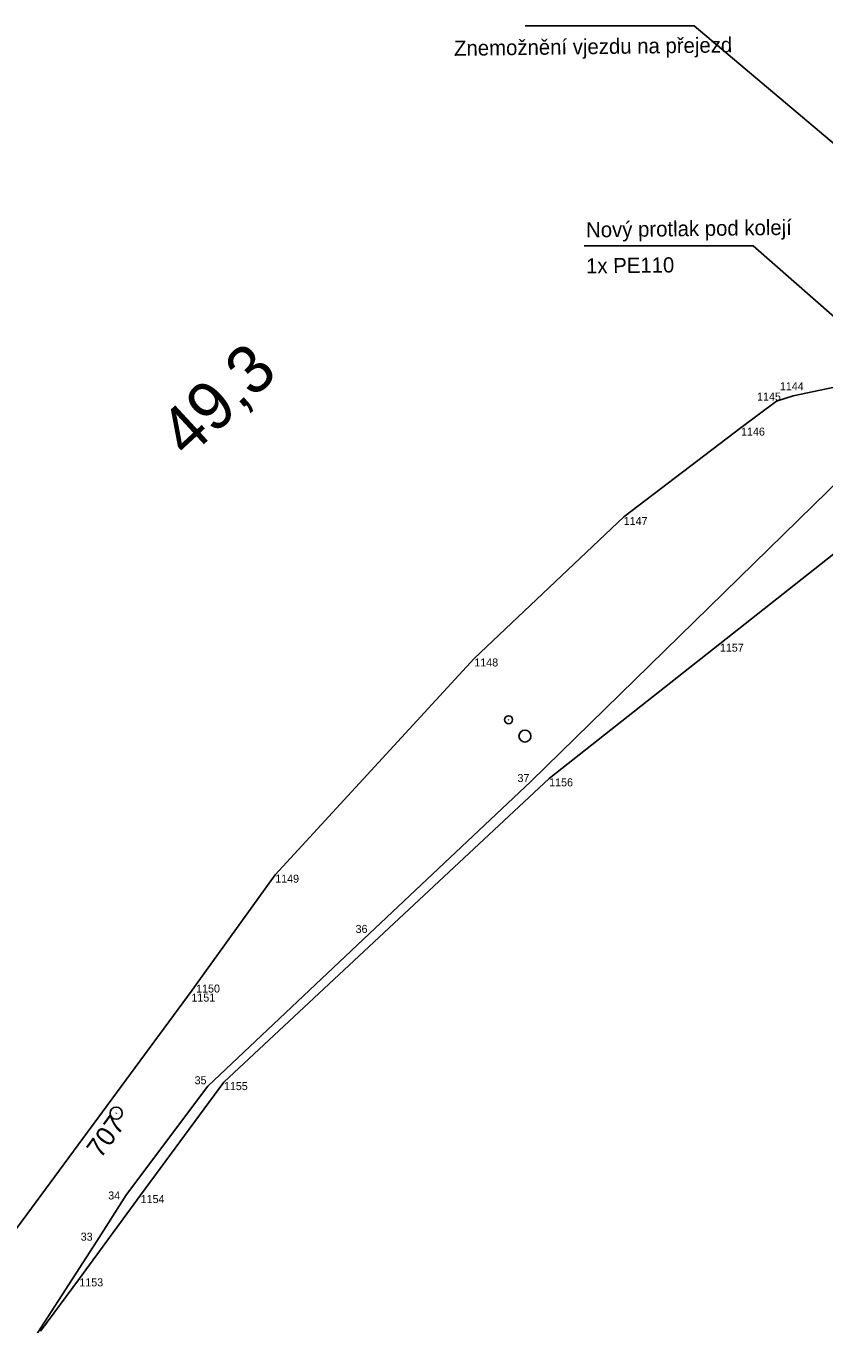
# Model space of a CAD drawing. Extents: x -678683 to -677755, y -1006946 to -1005971.
# Drawn here: x -678402.7 to -678303, y -1006633.5 to -1006471.2 of the extents above; entities that cross this region are included whole.
import ezdxf

# ---------------------------------------------------------------- set-up
doc = ezdxf.new("R2010")
doc.units = 0
for name, color, linetype in [('SSZT nové - lomové body', 7, 'Continuous'), ('SSZT_nové', 7, 'Continuous'), ('Stávající ŽBP', 7, 'Continuous'), ('SŽDC', 7, 'Continuous'), ('SŽDC - body', 7, 'Continuous'), ('Vrstva 7', 7, 'Continuous')]:
    doc.layers.add(name, color=color, linetype=linetype)

msp = doc.modelspace()

# ---------------------------------------------------------------- linework, layer by layer
at = {"layer": 'SSZT nové - lomové body'}
for p, q in [((-678339.66, -1006565.68), (-678339.66, -1006565.68)), ((-678359.84, -1006584.7), (-678359.84, -1006584.7)), ((-678380, -1006603.76), (-678380, -1006603.76)), ((-678390.13, -1006617.26), (-678390.13, -1006617.26)), ((-678393.87, -1006623.11), (-678393.87, -1006623.11))]:
    msp.add_line(p, q, dxfattribs=at)
at = {"layer": 'SSZT_nové'}
for p, q in [((-678319.24, -1006471.24), (-678340.35, -1006471.24)), ((-678319.24, -1006471.24), (-678285.44, -1006499.75)), ((-678311.88, -1006498.72), (-678332.99, -1006498.72)), ((-678311.88, -1006498.72), (-678293.71, -1006514.66))]:
    msp.add_line(p, q, dxfattribs=at)
msp.add_lwpolyline([(-678506.62, -1006791.94), (-678466.12, -1006753.23), (-678449.33, -1006728.75), (-678428.75, -1006695.61), (-678421.07, -1006681.97), (-678401.67, -1006635.24), (-678393.87, -1006623.11), (-678390.13, -1006617.26), (-678380, -1006603.76), (-678359.84, -1006584.7), (-678339.66, -1006565.68), (-678276.52, -1006503.93), (-678276.52, -1006503.93)], dxfattribs=at)
at = {"layer": 'Stávající ŽBP'}
msp.add_line((-678391.46, -1006607.15), (-678391.4, -1006607.07), dxfattribs=at)
msp.add_circle((-678391.43, -1006607.11), 0.756, dxfattribs=at)
at = {"layer": 'SŽDC'}
for p, q in [((-678297.37, -1006515.48), (-678306.89, -1006517.45)), ((-678308.95, -1006518.13), (-678313.38, -1006521.44)), ((-678306.89, -1006517.45), (-678308.95, -1006518.13)), ((-678313.38, -1006521.44), (-678328.04, -1006532.61)), ((-678328.04, -1006532.61), (-678346.7, -1006550.29)), ((-678316.02, -1006548.44), (-678299.42, -1006535.34)), ((-678337.35, -1006565.27), (-678316.02, -1006548.44)), ((-678346.7, -1006550.29), (-678371.57, -1006577.31)), ((-678377.98, -1006603.23), (-678337.35, -1006565.27)), ((-678371.57, -1006577.31), (-678381.45, -1006591.04)), ((-678388.38, -1006617.35), (-678377.98, -1006603.23)), ((-678396.04, -1006627.76), (-678388.38, -1006617.35)), ((-678400.89, -1006634.35), (-678396.04, -1006627.76))]:
    msp.add_line(p, q, dxfattribs=at)
msp.add_lwpolyline([(-678381.45, -1006591.04), (-678381.96, -1006591.73), (-678407.43, -1006626.27)], dxfattribs=at)
at = {"layer": 'SŽDC - body'}
for p, q in [((-678308.95, -1006518.13), (-678308.95, -1006518.13)), ((-678306.89, -1006517.45), (-678306.89, -1006517.45)), ((-678313.38, -1006521.44), (-678313.38, -1006521.44)), ((-678328.04, -1006532.61), (-678328.04, -1006532.61)), ((-678316.02, -1006548.44), (-678316.02, -1006548.44)), ((-678346.7, -1006550.29), (-678346.7, -1006550.29)), ((-678337.35, -1006565.27), (-678337.35, -1006565.27)), ((-678371.57, -1006577.31), (-678371.57, -1006577.31)), ((-678381.96, -1006591.73), (-678381.96, -1006591.73)), ((-678381.45, -1006591.04), (-678381.45, -1006591.04)), ((-678377.98, -1006603.23), (-678377.98, -1006603.23)), ((-678388.38, -1006617.35), (-678388.38, -1006617.35)), ((-678396.04, -1006627.76), (-678396.04, -1006627.76))]:
    msp.add_line(p, q, dxfattribs=at)
at = {"layer": 'Vrstva 7'}
msp.add_line((-678342.46, -1006557.98), (-678342.38, -1006557.92), dxfattribs=at)
for centre, radius in [((-678342.42, -1006557.95), 0.5), ((-678340.38, -1006559.98), 0.75)]:
    msp.add_circle(centre, radius, dxfattribs=at)

# ---------------------------------------------------------------- texts
at = {"layer": 'SSZT nové - lomové body'}
for s, p in [('37', (-678341.31, -1006565.73)), ('36', (-678361.53, -1006584.59)), ('35', (-678381.64, -1006603.5)), ('34', (-678392.43, -1006617.9)), ('33', (-678395.87, -1006623.05))]:
    msp.add_text(s, height=1, dxfattribs=at).set_placement(p)
at = {"layer": 'SSZT_nové'}
for s, p in [('Znemožnění vjezdu na přejezd', (-678349.22, -1006474.98)), ('Nový protlak pod kolejí', (-678332.73, -1006497.67)), ('1x PE110', (-678332.73, -1006502.18))]:
    msp.add_text(s, height=1.9, rotation=0.7098, dxfattribs=at).set_placement(p)
at = {"layer": 'Stávající ŽBP'}
msp.add_text('707', height=2.4, rotation=53.8375, dxfattribs=at).set_placement((-678393.37, -1006612.87))
at = {"layer": 'SŽDC - body'}
for s, p in [('1145', (-678311.38, -1006518.06)), ('1144', (-678308.53, -1006516.77)), ('1146', (-678313.38, -1006522.44)), ('1147', (-678328.04, -1006533.61)), ('1157', (-678316.02, -1006549.44)), ('1148', (-678346.7, -1006551.29)), ('1156', (-678337.35, -1006566.27)), ('1149', (-678371.57, -1006578.31)), ('1150', (-678381.45, -1006592.04)), ('1151', (-678382.04, -1006593.17)), ('1155', (-678377.98, -1006604.23)), ('1154', (-678388.38, -1006618.35)), ('1153', (-678396.04, -1006628.76))]:
    msp.add_text(s, height=1, dxfattribs=at).set_placement(p)
at = {"layer": 'Vrstva 7'}
msp.add_text('49,3', height=6, rotation=42.7281, dxfattribs=at).set_placement((-678382.53, -1006525.41))

doc.saveas('drawing.dxf')
